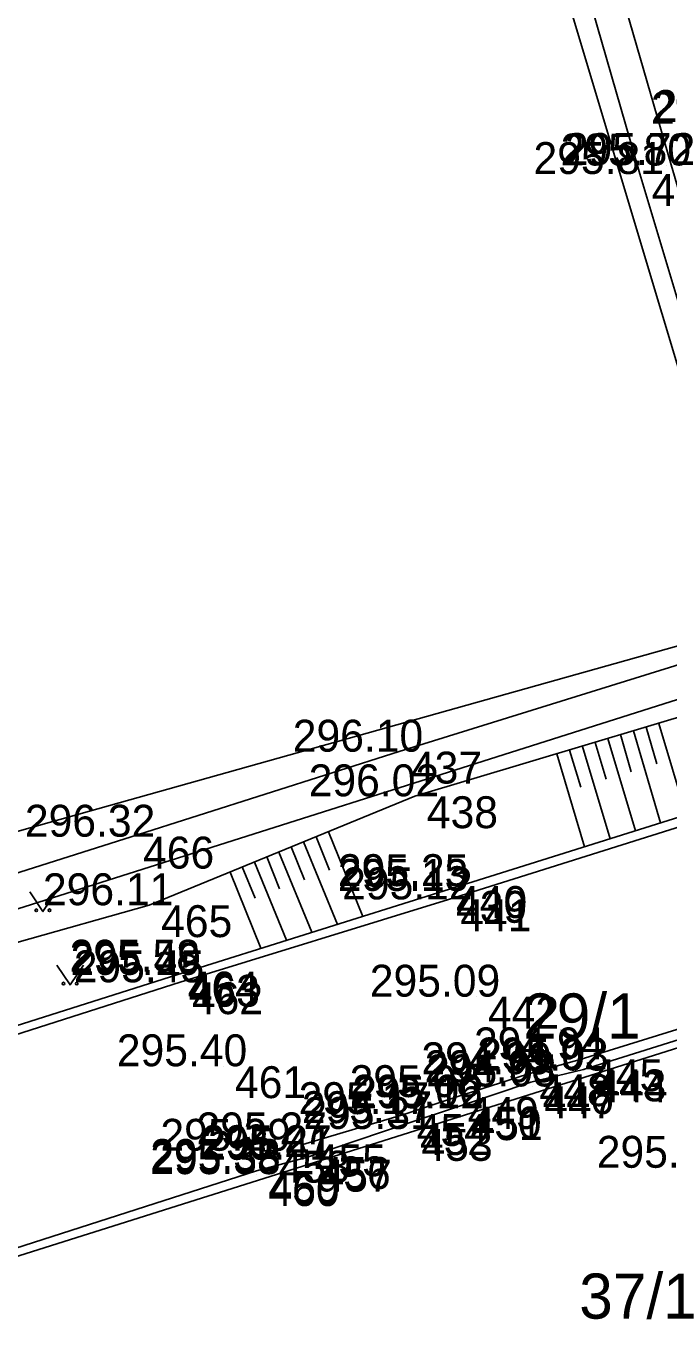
# Model space of a CAD drawing. Extents: x -599970 to -599524, y -1154772 to -1154457.
# Drawn here: x -599793.37 to -599781.27, y -1154687.91 to -1154663.25 of the extents above; entities that cross this region are included whole.
import ezdxf

# ---------------------------------------------------------------- set-up
doc = ezdxf.new("R2010")
doc.units = 0
for name, color, linetype in [('Z-KANALIZACNI SACHTY VPUSTI', 7, 'Continuous'), ('Z-KATASTRALNI MAPA', 7, 'Continuous'), ('Z-PLOT DREVENY', 7, 'Continuous'), ('Z-PODROBNE BODY', 7, 'Continuous'), ('Z-PODROBNE BODY-CISLO', 7, 'Continuous'), ('Z-PODROBNE BODY-VYSKA', 7, 'Continuous'), ('Z-SRAFOVANI SVAHU', 7, 'Continuous'), ('Z-STROMY ZNACKY KULTUR', 7, 'Continuous'), ('Z-TERENNI HRANY PATY', 7, 'Continuous'), ('Z-ZPEVNENE PLOCHY', 7, 'Continuous')]:
    doc.layers.add(name, color=color, linetype=linetype)

msp = doc.modelspace()

# ---------------------------------------------------------------- linework, layer by layer
at = {"layer": 'Z-KANALIZACNI SACHTY VPUSTI'}
msp.add_line((-599788.965, -1154684.41), (-599788.715, -1154684.41), dxfattribs=at)
msp.add_lwpolyline([(-599788.965, -1154684.535), (-599788.715, -1154684.535), (-599788.715, -1154684.285), (-599788.965, -1154684.285)], close=True, dxfattribs=at)
at = {"layer": 'Z-KATASTRALNI MAPA'}
msp.add_line((-599779.39, -1154675.37), (-599848.12, -1154697.2), dxfattribs=at)
for points in [[(-599779.65, -1154674.5), (-599784.9, -1154657), (-599786.85, -1154655.89), (-599787.57, -1154653.53), (-599785.79, -1154652.94), (-599792.35, -1154631.92), (-599798.2, -1154633.66), (-599805.39, -1154642.63)], [(-599834.98, -1154699.48), (-599751.66, -1154673.18), (-599740.79, -1154669.9), (-599738.46, -1154669.48), (-599735.86, -1154669.61), (-599733.7, -1154670.53), (-599731.62, -1154671.85), (-599729.9, -1154673.34)], [(-599779.65, -1154674.5), (-599852.06, -1154694.84), (-599855.48, -1154695.93)]]:
    msp.add_lwpolyline(points, dxfattribs=at)
at = {"layer": 'Z-PLOT DREVENY'}
for points in [[(-599779.22, -1154674.68), (-599781.82, -1154666.03), (-599784.68, -1154656.11), (-599785.66, -1154655.83), (-599787.35, -1154656.31)], [(-599812.56, -1154685.16), (-599801.32, -1154681.65), (-599791.39, -1154678.5), (-599786.35, -1154676.9), (-599779.22, -1154674.68)]]:
    msp.add_lwpolyline(points, dxfattribs=at)
at = {"layer": 'Z-PODROBNE BODY'}
for p, q in [((-599781.82, -1154666.03), (-599781.82, -1154666.03)), ((-599781.31, -1154665.87), (-599781.31, -1154665.87)), ((-599786.35, -1154676.9), (-599786.35, -1154676.9)), ((-599786.05, -1154677.74), (-599786.05, -1154677.74)), ((-599791.39, -1154678.5), (-599791.39, -1154678.5)), ((-599785.5, -1154679.43), (-599785.5, -1154679.43)), ((-599785.5, -1154679.52), (-599785.5, -1154679.52)), ((-599791.05, -1154679.79), (-599791.05, -1154679.79)), ((-599785.42, -1154679.68), (-599785.42, -1154679.68)), ((-599790.55, -1154681.04), (-599790.55, -1154681.04)), ((-599790.53, -1154681.1), (-599790.53, -1154681.1)), ((-599790.47, -1154681.24), (-599790.47, -1154681.24)), ((-599784.9, -1154681.51), (-599784.9, -1154681.51)), ((-599789.66, -1154682.82), (-599789.66, -1154682.82)), ((-599782.94, -1154682.69), (-599782.94, -1154682.69)), ((-599783.93, -1154682.97), (-599783.93, -1154682.97)), ((-599782.88, -1154682.88), (-599782.88, -1154682.88)), ((-599782.86, -1154682.9), (-599782.86, -1154682.9)), ((-599783.87, -1154683.12), (-599783.87, -1154683.12)), ((-599783.84, -1154683.2), (-599783.84, -1154683.2)), ((-599785.28, -1154683.4), (-599785.28, -1154683.4)), ((-599785.23, -1154683.58), (-599785.23, -1154683.58)), ((-599786.24, -1154683.72), (-599786.24, -1154683.72)), ((-599785.21, -1154683.61), (-599785.21, -1154683.61)), ((-599786.18, -1154683.89), (-599786.18, -1154683.89)), ((-599786.15, -1154684), (-599786.15, -1154684)), ((-599788.16, -1154684.29), (-599788.16, -1154684.29)), ((-599788.84, -1154684.41), (-599788.84, -1154684.41)), ((-599788.07, -1154684.53), (-599788.07, -1154684.53)), ((-599789.03, -1154684.79), (-599789.03, -1154684.79)), ((-599788.05, -1154684.58), (-599788.05, -1154684.58)), ((-599789.03, -1154684.85), (-599789.03, -1154684.85))]:
    msp.add_line(p, q, dxfattribs=at)
at = {"layer": 'Z-SRAFOVANI SVAHU'}
for points in [[(-599781.7, -1154676.44), (-599781.5, -1154677.13)], [(-599781.46, -1154676.37), (-599780.95, -1154678.09)], [(-599782.42, -1154676.65), (-599781.9, -1154678.39)], [(-599782.18, -1154676.58), (-599781.98, -1154677.28)], [(-599781.94, -1154676.51), (-599781.43, -1154678.24)], [(-599783.14, -1154676.87), (-599782.93, -1154677.57)], [(-599782.9, -1154676.8), (-599782.38, -1154678.54)], [(-599782.66, -1154676.73), (-599782.45, -1154677.42)], [(-599783.38, -1154676.94), (-599782.86, -1154678.69)], [(-599787.68, -1154678.41), (-599787.03, -1154680)], [(-599788.15, -1154678.6), (-599787.51, -1154680.15)], [(-599787.91, -1154678.5), (-599787.66, -1154679.13)], [(-599788.84, -1154678.88), (-599788.6, -1154679.48)], [(-599788.61, -1154678.79), (-599787.99, -1154680.3)], [(-599788.38, -1154678.69), (-599788.13, -1154679.31)], [(-599789.3, -1154679.07), (-599789.06, -1154679.66)], [(-599789.07, -1154678.98), (-599788.47, -1154680.45)], [(-599789.53, -1154679.17), (-599788.95, -1154680.6)]]:
    msp.add_lwpolyline(points, dxfattribs=at)
at = {"layer": 'Z-STROMY ZNACKY KULTUR'}
for points in [[(-599793.3, -1154679.535), (-599793.05, -1154679.91), (-599792.8, -1154679.535)], [(-599792.79, -1154680.915), (-599792.54, -1154681.29), (-599792.29, -1154680.915)]]:
    msp.add_lwpolyline(points, dxfattribs=at)
for centre in [(-599793.175, -1154679.885), (-599792.925, -1154679.885), (-599792.665, -1154681.265), (-599792.415, -1154681.265)]:
    msp.add_circle(centre, 0.025, dxfattribs=at)
at = {"layer": 'Z-TERENNI HRANY PATY'}
msp.add_lwpolyline([(-599778.47, -1154675.47), (-599786.05, -1154677.74), (-599791.05, -1154679.79), (-599801.02, -1154682.6), (-599812.13, -1154686.2)], dxfattribs=at)
at = {"layer": 'Z-ZPEVNENE PLOCHY'}
for points in [[(-599778.47, -1154675.47), (-599778.71, -1154674.46), (-599781.23, -1154665.86), (-599784.02, -1154656.22), (-599785.76, -1154654.87)], [(-599772.85, -1154675.54), (-599776.28, -1154676.63), (-599778.05, -1154677.18), (-599785.5, -1154679.52), (-599790.53, -1154681.1), (-599800.67, -1154684.32), (-599811.53, -1154687.77)], [(-599772.99, -1154675.74), (-599776.22, -1154676.81), (-599777.99, -1154677.34), (-599785.42, -1154679.68), (-599790.47, -1154681.24), (-599800.61, -1154684.48), (-599811.46, -1154687.9)], [(-599771.9, -1154679.45), (-599771.96, -1154679.27), (-599776.11, -1154680.57), (-599782.94, -1154682.69), (-599783.93, -1154682.97), (-599785.28, -1154683.4), (-599786.24, -1154683.72), (-599788.16, -1154684.29), (-599788.07, -1154684.53)], [(-599771.9, -1154679.45), (-599776.08, -1154680.75), (-599782.88, -1154682.88), (-599783.87, -1154683.12), (-599785.23, -1154683.58), (-599786.18, -1154683.89), (-599788.07, -1154684.53), (-599789.03, -1154684.79), (-599799.87, -1154688.27), (-599810.12, -1154691.54)]]:
    msp.add_lwpolyline(points, dxfattribs=at)

# ---------------------------------------------------------------- texts
at = {"layer": 'Z-KATASTRALNI MAPA'}
for s, p in [('29/1', (-599784.015, -1154682.3)), ('37/1', (-599782.96, -1154687.57))]:
    msp.add_text(s, height=0.85, dxfattribs=at).set_placement(p)
at = {"layer": 'Z-PODROBNE BODY-CISLO'}
for s, p in [(' 484', (-599781.82, -1154666.63)), (' 437', (-599786.35, -1154677.5)), (' 438', (-599786.05, -1154678.34)), (' 466', (-599791.39, -1154679.1)), (' 440', (-599785.5, -1154680.03)), (' 439', (-599785.5, -1154680.12)), (' 465', (-599791.05, -1154680.39)), (' 441', (-599785.42, -1154680.28)), (' 464', (-599790.55, -1154681.64)), (' 463', (-599790.53, -1154681.7)), (' 462', (-599790.47, -1154681.84)), (' 442', (-599784.9, -1154682.11)), (' 461', (-599789.66, -1154683.42)), (' 445', (-599782.94, -1154683.29)), (' 448', (-599783.93, -1154683.57)), (' 443', (-599782.88, -1154683.48)), (' 444', (-599782.86, -1154683.5)), (' 446', (-599783.87, -1154683.72)), (' 447', (-599783.84, -1154683.8)), (' 449', (-599785.28, -1154684)), (' 450', (-599785.23, -1154684.18)), (' 454', (-599786.24, -1154684.32)), (' 451', (-599785.21, -1154684.21)), (' 452', (-599786.18, -1154684.49)), (' 453', (-599786.15, -1154684.6)), (' 455', (-599788.16, -1154684.89)), (' 458', (-599788.84, -1154685.01)), (' 456', (-599788.07, -1154685.13)), (' 459', (-599789.03, -1154685.39)), (' 457', (-599788.05, -1154685.18)), (' 460', (-599789.03, -1154685.45))]:
    msp.add_text(s, height=0.6, dxfattribs=at).set_placement(p)
at = {"layer": 'Z-PODROBNE BODY-VYSKA'}
for s, p in [('295.68 ', (-599781.61, -1154665.08)), ('295.76 ', (-599781.56, -1154665.05)), ('295.80 ', (-599783.31, -1154665.87)), ('295.72 ', (-599783.23, -1154665.86)), ('295.81 ', (-599783.82, -1154666.03)), ('296.10 ', (-599788.35, -1154676.9)), ('296.02 ', (-599788.05, -1154677.74)), ('296.32 ', (-599793.39, -1154678.5)), ('295.25 ', (-599787.5, -1154679.43)), ('295.13 ', (-599787.5, -1154679.52)), ('295.12 ', (-599787.42, -1154679.68)), ('296.11 ', (-599793.05, -1154679.79)), ('295.58 ', (-599792.55, -1154681.04)), ('295.49 ', (-599792.53, -1154681.1)), ('295.45 ', (-599792.47, -1154681.24)), ('295.09 ', (-599786.9, -1154681.51)), ('294.94 ', (-599784.94, -1154682.69)), ('295.40 ', (-599791.66, -1154682.82)), ('294.92 ', (-599784.88, -1154682.88)), ('295.03 ', (-599784.86, -1154682.9)), ('294.99 ', (-599785.93, -1154682.97)), ('294.98 ', (-599785.87, -1154683.12)), ('295.03 ', (-599785.84, -1154683.2)), ('295.08 ', (-599787.28, -1154683.4)), ('295.06 ', (-599787.23, -1154683.58)), ('295.12 ', (-599787.21, -1154683.61)), ('295.17 ', (-599788.24, -1154683.72)), ('295.17 ', (-599788.18, -1154683.89)), ('295.31 ', (-599788.15, -1154684)), ('295.29 ', (-599790.84, -1154684.41)), ('295.27 ', (-599790.16, -1154684.29)), ('295.27 ', (-599790.07, -1154684.53)), ('295.41 ', (-599790.05, -1154684.58)), ('295.33 ', (-599791.03, -1154684.79)), ('295.38 ', (-599791.03, -1154684.85)), ('295.36 ', (-599782.63, -1154684.73))]:
    msp.add_text(s, height=0.6, dxfattribs=at).set_placement(p)

doc.saveas('drawing.dxf')
